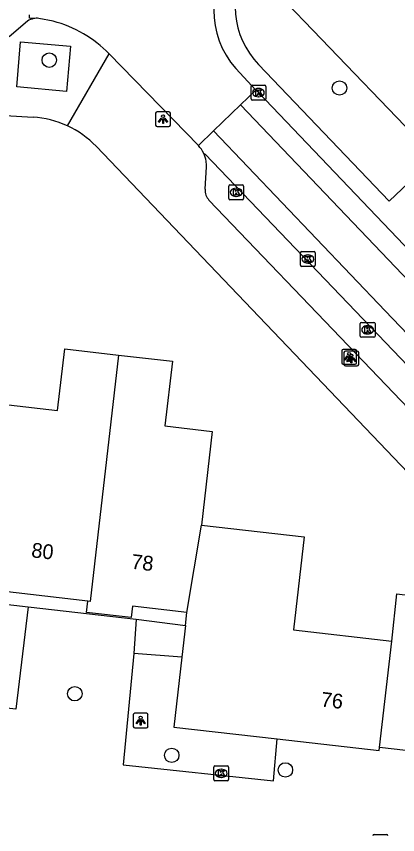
# Model space of a CAD drawing. Extents: x 162398 to 163643, y 386453 to 387397.
# Drawn here: x 162883.6 to 162909.4, y 386528.3 to 386583.8 of the extents above; entities that cross this region are included whole.
import ezdxf

# ---------------------------------------------------------------- set-up
doc = ezdxf.new("R2010")
doc.units = 0
for name, color, linetype in [('IMGEO_Boom', 7, 'Continuous'), ('IMGEO_Groenvoorziening', 7, 'Continuous'), ('IMGEO_Kolk', 7, 'Continuous'), ('IMGEO_Lichtpunt', 7, 'Continuous'), ('IMGEO_Pand', 7, 'Continuous'), ('IMGEO_Pand_nummerreeks', 7, 'Continuous'), ('IMGEO_Rijbaan_lokaal_gesloten', 7, 'Continuous'), ('IMGEO_Rijbaan_lokaal_open', 7, 'Continuous'), ('IMGEO_Rioolput', 7, 'Continuous'), ('IMGEO_Voetpad_open', 7, 'Continuous')]:
    doc.layers.add(name, color=color, linetype=linetype)

msp = doc.modelspace()

# ---------------------------------------------------------------- linework, layer by layer
at = {"layer": 'IMGEO_Boom'}
for centre in [(162885.801, 386580.84), (162905.465, 386578.949), (162887.532, 386537.875), (162894.098, 386533.699), (162901.801, 386532.708)]:
    msp.add_circle(centre, 0.489, dxfattribs=at)
at = {"layer": 'IMGEO_Groenvoorziening'}
for points in [[(162900.182, 386586.506), (162903.668, 386582.872), (162911.033, 386575.194)], [(162877.944, 386544.524), (162884.37, 386543.773)], [(162891.681, 386542.925), (162895.032, 386542.51)]]:
    msp.add_lwpolyline(points, dxfattribs=at)
at = {"layer": 'IMGEO_Kolk'}
for p, q in [((162899.471, 386578.21), (162899.471, 386579.062)), ((162899.546, 386579.136), (162900.398, 386579.136)), ((162899.959, 386578.916), (162899.984, 386578.916)), ((162900.472, 386579.062), (162900.472, 386578.21)), ((162899.982, 386578.356), (162899.957, 386578.356)), ((162900.398, 386578.136), (162899.546, 386578.136)), ((162897.967, 386571.449), (162897.967, 386572.301)), ((162898.042, 386572.375), (162898.894, 386572.375)), ((162898.455, 386572.155), (162898.48, 386572.155)), ((162898.968, 386572.301), (162898.968, 386571.449)), ((162898.478, 386571.595), (162898.453, 386571.595)), ((162898.894, 386571.375), (162898.042, 386571.375)), ((162902.821, 386566.928), (162902.821, 386567.78)), ((162902.896, 386567.854), (162903.748, 386567.854)), ((162903.822, 386567.78), (162903.822, 386566.928)), ((162903.309, 386567.634), (162903.334, 386567.634)), ((162903.748, 386566.854), (162902.896, 386566.854)), ((162903.332, 386567.074), (162903.307, 386567.074)), ((162906.87, 386562.127), (162906.87, 386562.979)), ((162906.945, 386563.053), (162907.797, 386563.053)), ((162907.358, 386562.833), (162907.383, 386562.833)), ((162907.871, 386562.979), (162907.871, 386562.127)), ((162907.381, 386562.273), (162907.356, 386562.273)), ((162907.797, 386562.053), (162906.945, 386562.053)), ((162896.953, 386532.051), (162896.953, 386532.903)), ((162897.028, 386532.977), (162897.88, 386532.977)), ((162897.441, 386532.757), (162897.466, 386532.757)), ((162897.954, 386532.903), (162897.954, 386532.051)), ((162897.464, 386532.197), (162897.439, 386532.197)), ((162897.88, 386531.977), (162897.028, 386531.977))]:
    msp.add_line(p, q, dxfattribs=at)
for points in [[(162899.471, 386578.21), (162899.471, 386579.062)], [(162899.546, 386579.136), (162900.398, 386579.136)], [(162899.792, 386578.836), (162899.915, 386578.836), (162899.915, 386578.685), (162900.045, 386578.836), (162900.209, 386578.836), (162900.063, 386578.685), (162900.216, 386578.436), (162900.064, 386578.436), (162899.979, 386578.6), (162899.915, 386578.533), (162899.915, 386578.436), (162899.792, 386578.436), (162899.792, 386578.836)], [(162900.472, 386579.062), (162900.472, 386578.21)], [(162900.398, 386578.136), (162899.546, 386578.136)], [(162897.967, 386571.449), (162897.967, 386572.301)], [(162898.042, 386572.375), (162898.894, 386572.375)], [(162898.968, 386572.301), (162898.968, 386571.449)], [(162898.288, 386572.075), (162898.411, 386572.075), (162898.411, 386571.924), (162898.541, 386572.075), (162898.705, 386572.075), (162898.559, 386571.924), (162898.712, 386571.675), (162898.56, 386571.675), (162898.475, 386571.839), (162898.411, 386571.772), (162898.411, 386571.675), (162898.288, 386571.675), (162898.288, 386572.075)], [(162898.894, 386571.375), (162898.042, 386571.375)], [(162902.821, 386566.928), (162902.821, 386567.78)], [(162902.896, 386567.854), (162903.748, 386567.854)], [(162903.822, 386567.78), (162903.822, 386566.928)], [(162903.142, 386567.554), (162903.265, 386567.554), (162903.265, 386567.403), (162903.395, 386567.554), (162903.559, 386567.554), (162903.413, 386567.403), (162903.566, 386567.154), (162903.414, 386567.154), (162903.329, 386567.318), (162903.265, 386567.251), (162903.265, 386567.154), (162903.142, 386567.154), (162903.142, 386567.554)], [(162903.748, 386566.854), (162902.896, 386566.854)], [(162906.87, 386562.127), (162906.87, 386562.979)], [(162906.945, 386563.053), (162907.797, 386563.053)], [(162907.191, 386562.753), (162907.314, 386562.753), (162907.314, 386562.602), (162907.444, 386562.753), (162907.608, 386562.753), (162907.462, 386562.602), (162907.615, 386562.353), (162907.463, 386562.353), (162907.378, 386562.517), (162907.314, 386562.45), (162907.314, 386562.353), (162907.191, 386562.353), (162907.191, 386562.753)], [(162907.871, 386562.979), (162907.871, 386562.127)], [(162907.797, 386562.053), (162906.945, 386562.053)], [(162896.953, 386532.051), (162896.953, 386532.903)], [(162897.028, 386532.977), (162897.88, 386532.977)], [(162897.954, 386532.903), (162897.954, 386532.051)], [(162897.274, 386532.677), (162897.397, 386532.677), (162897.397, 386532.526), (162897.527, 386532.677), (162897.691, 386532.677), (162897.545, 386532.526), (162897.698, 386532.277), (162897.546, 386532.277), (162897.461, 386532.441), (162897.397, 386532.374), (162897.397, 386532.277), (162897.274, 386532.277), (162897.274, 386532.677)], [(162897.88, 386531.977), (162897.028, 386531.977)]]:
    msp.add_lwpolyline(points, dxfattribs=at)
for centre, start, end in [((162899.548, 386579.06), 91.552, 178.448), ((162899.548, 386579.06), 91.552, 178.448), ((162900.396, 386579.06), 1.552, 88.448), ((162900.396, 386579.06), 1.552, 88.448), ((162899.548, 386578.212), 181.552, 268.448), ((162899.548, 386578.212), 181.552, 268.448), ((162900.396, 386578.212), 271.552, 358.448), ((162900.396, 386578.212), 271.552, 358.448), ((162898.044, 386572.299), 91.552, 178.448), ((162898.044, 386572.299), 91.552, 178.448), ((162898.892, 386572.299), 1.552, 88.448), ((162898.892, 386572.299), 1.552, 88.448), ((162898.044, 386571.451), 181.552, 268.448), ((162898.044, 386571.451), 181.552, 268.448), ((162898.892, 386571.451), 271.552, 358.448), ((162898.892, 386571.451), 271.552, 358.448), ((162902.898, 386567.778), 91.552, 178.448), ((162902.898, 386567.778), 91.552, 178.448), ((162903.746, 386567.778), 1.552, 88.448), ((162903.746, 386567.778), 1.552, 88.448), ((162902.898, 386566.93), 181.552, 268.448), ((162902.898, 386566.93), 181.552, 268.448), ((162903.746, 386566.93), 271.552, 358.448), ((162903.746, 386566.93), 271.552, 358.448), ((162906.947, 386562.977), 91.552, 178.448), ((162906.947, 386562.977), 91.552, 178.448), ((162907.795, 386562.977), 1.552, 88.448), ((162907.795, 386562.977), 1.552, 88.448), ((162906.947, 386562.129), 181.552, 268.448), ((162906.947, 386562.129), 181.552, 268.448), ((162907.795, 386562.129), 271.552, 358.448), ((162907.795, 386562.129), 271.552, 358.448), ((162897.03, 386532.901), 91.552, 178.448), ((162897.03, 386532.901), 91.552, 178.448), ((162897.878, 386532.901), 1.552, 88.448), ((162897.878, 386532.901), 1.552, 88.448), ((162897.03, 386532.053), 181.552, 268.448), ((162897.03, 386532.053), 181.552, 268.448), ((162897.878, 386532.053), 271.552, 358.448), ((162897.878, 386532.053), 271.552, 358.448)]:
    msp.add_arc(centre, 0.0765, start, end, dxfattribs=at)
for centre, major_axis, ratio, start_param, end_param in [((162899.958, 386578.636), (-0.387, 0.002), 0.722429, 4.712389, 7.853982), ((162899.983, 386578.636), (-0.39, 0.002), 0.717154, 1.570796, 4.712389), ((162898.454, 386571.875), (-0.387, 0.002), 0.722429, 4.712389, 7.853982), ((162898.479, 386571.875), (-0.39, 0.002), 0.717154, 1.570796, 4.712389), ((162903.308, 386567.354), (-0.387, 0.002), 0.722429, 4.712389, 7.853982), ((162903.333, 386567.354), (-0.39, 0.002), 0.717154, 1.570796, 4.712389), ((162907.357, 386562.553), (-0.387, 0.002), 0.722429, 4.712389, 7.853982), ((162907.382, 386562.553), (-0.39, 0.002), 0.717154, 1.570796, 4.712389), ((162897.44, 386532.477), (-0.387, 0.002), 0.722429, 4.712389, 7.853982), ((162897.465, 386532.477), (-0.39, 0.002), 0.717154, 1.570796, 4.712389)]:
    msp.add_ellipse(centre, major_axis=major_axis, ratio=ratio, start_param=start_param, end_param=end_param, dxfattribs=at)
at = {"layer": 'IMGEO_Lichtpunt'}
for p, q in [((162893.011, 386577.244), (162893.011, 386576.437)), ((162893.011, 386577.244), (162893.011, 386576.437)), ((162893.913, 386577.339), (162893.105, 386577.339)), ((162893.913, 386577.339), (162893.105, 386577.339)), ((162894.007, 386576.437), (162894.007, 386577.244)), ((162894.007, 386576.437), (162894.007, 386577.244)), ((162893.105, 386576.343), (162893.913, 386576.343)), ((162893.105, 386576.343), (162893.913, 386576.343)), ((162905.617, 386561.121), (162905.617, 386560.314)), ((162905.617, 386561.121), (162905.617, 386560.314)), ((162906.519, 386561.216), (162905.711, 386561.216)), ((162906.519, 386561.216), (162905.711, 386561.216)), ((162905.768, 386561.009), (162905.768, 386560.202)), ((162905.768, 386561.009), (162905.768, 386560.202)), ((162906.67, 386561.104), (162905.862, 386561.104)), ((162906.67, 386561.104), (162905.862, 386561.104)), ((162906.613, 386560.314), (162906.613, 386561.121)), ((162906.613, 386560.314), (162906.613, 386561.121)), ((162906.764, 386560.202), (162906.764, 386561.009)), ((162906.764, 386560.202), (162906.764, 386561.009)), ((162905.711, 386560.22), (162906.519, 386560.22)), ((162905.711, 386560.22), (162906.519, 386560.22)), ((162905.862, 386560.108), (162906.67, 386560.108)), ((162905.862, 386560.108), (162906.67, 386560.108)), ((162891.496, 386536.456), (162891.496, 386535.649)), ((162891.496, 386536.456), (162891.496, 386535.649)), ((162892.398, 386536.551), (162891.59, 386536.551)), ((162892.398, 386536.551), (162891.59, 386536.551)), ((162892.492, 386535.649), (162892.492, 386536.456)), ((162892.492, 386535.649), (162892.492, 386536.456)), ((162891.59, 386535.555), (162892.398, 386535.555)), ((162891.59, 386535.555), (162892.398, 386535.555))]:
    msp.add_line(p, q, dxfattribs=at)
for points in [[(162893.385, 386576.908), (162893.424, 386576.88), (162893.236, 386576.618), (162893.198, 386576.645), (162893.385, 386576.908)], [(162893.487, 386576.86), (162893.534, 386576.86), (162893.534, 386576.538), (162893.487, 386576.538), (162893.487, 386576.86)], [(162893.597, 386576.88), (162893.635, 386576.907), (162893.822, 386576.645), (162893.783, 386576.617), (162893.597, 386576.88)], [(162905.991, 386560.785), (162906.03, 386560.757), (162905.842, 386560.495), (162905.804, 386560.522), (162905.991, 386560.785)], [(162906.142, 386560.673), (162906.181, 386560.645), (162905.993, 386560.383), (162905.955, 386560.41), (162906.142, 386560.673)], [(162906.093, 386560.737), (162906.14, 386560.737), (162906.14, 386560.415), (162906.093, 386560.415), (162906.093, 386560.737)], [(162906.203, 386560.757), (162906.241, 386560.784), (162906.428, 386560.522), (162906.389, 386560.494), (162906.203, 386560.757)], [(162906.244, 386560.625), (162906.291, 386560.625), (162906.291, 386560.303), (162906.244, 386560.303), (162906.244, 386560.625)], [(162906.354, 386560.645), (162906.392, 386560.672), (162906.579, 386560.41), (162906.54, 386560.382), (162906.354, 386560.645)], [(162891.87, 386536.12), (162891.909, 386536.092), (162891.721, 386535.83), (162891.683, 386535.857), (162891.87, 386536.12)], [(162891.972, 386536.072), (162892.019, 386536.072), (162892.019, 386535.75), (162891.972, 386535.75), (162891.972, 386536.072)], [(162892.082, 386536.092), (162892.12, 386536.119), (162892.307, 386535.857), (162892.268, 386535.829), (162892.082, 386536.092)]]:
    msp.add_lwpolyline(points, dxfattribs=at)
for centre in [(162893.51, 386577.042), (162906.116, 386560.919), (162906.267, 386560.807), (162891.995, 386536.254)]:
    msp.add_circle(centre, 0.0994, dxfattribs=at)
for centre, start, end in [((162893.105, 386577.244), 90, 180), ((162893.105, 386577.244), 90, 180), ((162893.913, 386577.244), 0, 90), ((162893.913, 386577.244), 0, 90), ((162893.105, 386576.437), 180, 270), ((162893.105, 386576.437), 180, 270), ((162893.913, 386576.437), 270, 0), ((162893.913, 386576.437), 270, 360), ((162905.711, 386561.121), 90, 180), ((162905.711, 386561.121), 90, 180), ((162905.862, 386561.009), 90, 180), ((162905.862, 386561.009), 90, 180), ((162906.519, 386561.121), 0, 90), ((162906.519, 386561.121), 0, 90), ((162906.67, 386561.009), 0, 90), ((162906.67, 386561.009), 0, 90), ((162905.711, 386560.314), 180, 270), ((162905.711, 386560.314), 180, 270), ((162905.862, 386560.202), 180, 270), ((162905.862, 386560.202), 180, 270), ((162906.519, 386560.314), 270, 0), ((162906.519, 386560.314), 270, 360), ((162906.67, 386560.202), 270, 0), ((162906.67, 386560.202), 270, 360), ((162891.59, 386536.456), 90, 180), ((162891.59, 386536.456), 90, 180), ((162892.398, 386536.456), 0, 90), ((162892.398, 386536.456), 0, 90), ((162891.59, 386535.649), 180, 270), ((162891.59, 386535.649), 180, 270), ((162892.398, 386535.649), 270, 0), ((162892.398, 386535.649), 270, 360)]:
    msp.add_arc(centre, 0.0946, start, end, dxfattribs=at)
at = {"layer": 'IMGEO_Pand'}
for points in [[(162883.043, 386557.469), (162886.369, 386557.087), (162886.849, 386561.263), (162890.498, 386560.843)], [(162890.498, 386560.843), (162888.576, 386544.137), (162888.42, 386544.155)], [(162890.498, 386560.843), (162894.147, 386560.423), (162893.642, 386556.032), (162896.842, 386555.664), (162896.111, 386549.314)], [(162895.133, 386543.382), (162896.111, 386549.314)], [(162896.111, 386549.314), (162903.068, 386548.513), (162902.344, 386542.218), (162909.011, 386541.45)], [(162888.42, 386544.155), (162881.592, 386544.94)], [(162895.133, 386543.382), (162891.437, 386543.808), (162891.349, 386543.041), (162888.332, 386543.388), (162888.42, 386544.155)], [(162895.032, 386542.51), (162895.133, 386543.382)], [(162895.032, 386542.51), (162894.785, 386540.363)], [(162908.182, 386534.239), (162909.011, 386541.45)], [(162894.785, 386540.363), (162894.239, 386535.617), (162901.244, 386534.811)], [(162901.244, 386534.811), (162908.156, 386534.015), (162908.182, 386534.239)]]:
    msp.add_lwpolyline(points, dxfattribs=at)
at = {"layer": 'IMGEO_Rijbaan_lokaal_gesloten'}
for points in [[(162912.252, 386565.764), (162911.724, 386566.328), (162899.972, 386578.636), (162899.807, 386578.798)], [(162898.769, 386577.801), (162910.688, 386565.306), (162927.247, 386548.019), (162937.051, 386537.73)]]:
    msp.add_lwpolyline(points, dxfattribs=at)
at = {"layer": 'IMGEO_Rijbaan_lokaal_open'}
for points in [[(162884.742, 386583.656), (162884.453, 386583.681), (162884.473, 386583.919)], [(162886.072, 386583.474), (162885.087, 386583.67)], [(162889.856, 386581.264), (162895.903, 386575.044)], [(162899.807, 386578.798), (162898.44, 386580.27)], [(162898.769, 386577.801), (162899.807, 386578.798)], [(162896.93, 386576.053), (162898.769, 386577.801)], [(162895.903, 386575.044), (162896.93, 386576.053)], [(162935.196, 386535.999), (162928.541, 386542.947), (162908.569, 386563.845), (162896.93, 386576.053)], [(162896.266, 386574.519), (162896.361, 386574.474), (162927.42, 386542.002), (162927.552, 386541.858)], [(162884.37, 386543.773), (162883.549, 386536.834), (162877.141, 386537.537), (162877.944, 386544.524)], [(162884.37, 386543.773), (162891.681, 386542.925)], [(162891.681, 386542.925), (162891.535, 386540.603)], [(162891.535, 386540.603), (162890.812, 386533.048), (162900.985, 386531.959), (162901.244, 386534.811)], [(162911.735, 386533.821), (162908.182, 386534.239)]]:
    msp.add_lwpolyline(points, dxfattribs=at)
for centre, radius, start, end in [((162902.909, 386584.22), 5.964, 138.2273, 221.469), ((162884.961, 386582.525), 1.152, 83.7049, 100.9426), ((162884.073, 386575.706), 8.021, 43.8607, 75.5662), ((162894.515, 386573.696), 1.935, 25.1677, 44.1545)]:
    msp.add_arc(centre, radius, start, end, dxfattribs=at)
at = {"layer": 'IMGEO_Rioolput'}
msp.add_line((162907.808, 386528.32), (162908.66, 386528.32), dxfattribs=at)
msp.add_lwpolyline([(162907.808, 386528.32), (162908.66, 386528.32)], dxfattribs=at)
for centre, start, end in [((162907.81, 386528.244), 91.552, 178.448), ((162907.81, 386528.244), 91.552, 178.448), ((162908.658, 386528.244), 1.552, 88.448), ((162908.658, 386528.244), 1.552, 88.448)]:
    msp.add_arc(centre, 0.0765, start, end, dxfattribs=at)
at = {"layer": 'IMGEO_Voetpad_open'}
for points in [[(162884.333, 386583.482), (162883.083, 386582.418)], [(162883.862, 386582.086), (162887.243, 386581.797), (162886.967, 386578.719), (162883.597, 386579.023), (162883.862, 386582.086)], [(162887.029, 386576.387), (162889.856, 386581.264)], [(162911.033, 386575.194), (162910.745, 386574.918), (162910.146, 386574.344), (162911.015, 386573.361), (162908.821, 386571.279), (162899.983, 386580.542)], [(162863.449, 386578.248), (162884.706, 386576.972)], [(162912.873, 386544.224), (162913.466, 386549.351), (162888.98, 386574.996)], [(162896.372, 386572.085), (162896.446, 386573.615)], [(162923.891, 386542.84), (162906.575, 386560.94), (162896.624, 386571.352)], [(162909.011, 386541.45), (162909.344, 386544.646), (162912.873, 386544.224)], [(162894.785, 386540.363), (162891.535, 386540.603)]]:
    msp.add_lwpolyline(points, dxfattribs=at)
for centre, radius, start, end in [((162903.963, 386584.417), 5.555, 145.2359, 224.2294), ((162884.959, 386582.579), 1.099, 101.377, 124.7155), ((162884.316, 386570.519), 6.465, 65.1876, 86.5427), ((162884.315, 386570.517), 6.467, 43.8358, 65.1889), ((162894.516, 386573.7), 1.932, 8.6958, 25.0814), ((162894.467, 386573.699), 1.981, 357.5689, 8.5045), ((162897.254, 386571.978), 0.888, 173.0945, 224.8507)]:
    msp.add_arc(centre, radius, start, end, dxfattribs=at)

# ---------------------------------------------------------------- texts
at = {"layer": 'IMGEO_Pand_nummerreeks'}
for s, rotation, p in [('80', 353.4339, (162884.554, 386547.137)), ('78', 353.4339, (162891.325, 386546.357)), ('76', 353.4306, (162904.168, 386537.011))]:
    msp.add_text(s, height=1, rotation=rotation, dxfattribs=at).set_placement(p)

doc.saveas('drawing.dxf')
